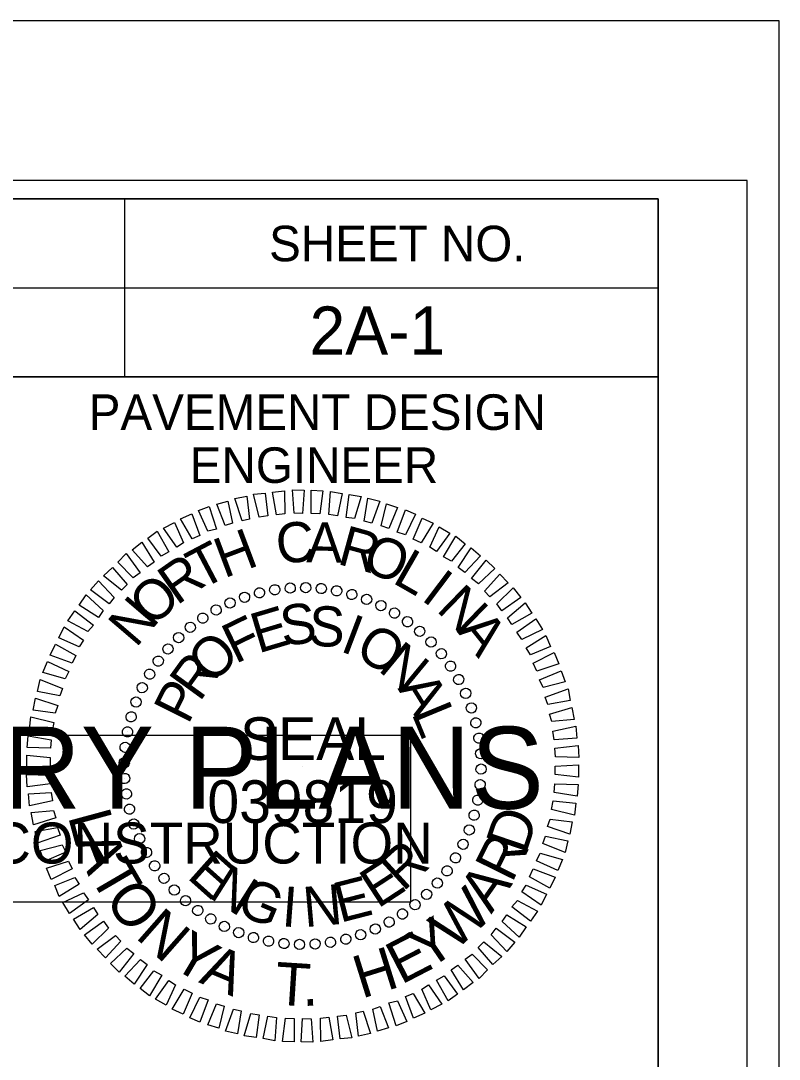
# Model space of a CAD drawing. Extents: x 573786 to 574032, y -53324 to -53148.
# Drawn here: x 574002.74 to 574013.4, y -53229.04 to -53214.45 of the extents above; entities that cross this region are included whole.
import ezdxf

# ---------------------------------------------------------------- set-up
doc = ezdxf.new("R2010")
doc.units = 0
for name, color, linetype in [('Sheet Cutting Line CELL', 7, 'Continuous'), ('Sheet Data Field CELL', 7, 'Continuous'), ('Sheet Plot Border Inside CELL', 7, 'Continuous'), ('Sheet Plot Border Outside CELL', 7, 'Continuous'), ('Sheet Professional Seal CELL', 7, 'Continuous'), ('Sheet Sticker Preliminary CELL', 7, 'Continuous'), ('Sheet Typical CELL', 7, 'Continuous')]:
    doc.layers.add(name, color=color, linetype=linetype)

msp = doc.modelspace()

# ---------------------------------------------------------------- linework, layer by layer
at = {"layer": 'Sheet Cutting Line CELL'}
msp.add_line((574013.401, -53214.447), (573845.001, -53214.447), dxfattribs=at)
at = {"layer": 'Sheet Plot Border Inside CELL'}
msp.add_lwpolyline([(574012.951, -53216.692), (573846.301, -53216.692), (573846.301, -53322.202), (574012.951, -53322.202)], close=True, dxfattribs=at)
at = {"layer": 'Sheet Plot Border Outside CELL'}
msp.add_lwpolyline([(574013.401, -53214.447), (573845.001, -53214.447), (573845.001, -53324.447), (574013.401, -53324.447)], close=True, dxfattribs=at)
at = {"layer": 'Sheet Professional Seal CELL'}
for p, q in [((574005.883, -53222.546), (574005.883, -53222.546)), ((574006.093, -53222.486), (574006.093, -53222.486)), ((574006.313, -53222.446), (574006.313, -53222.446)), ((574006.528, -53222.416), (574006.528, -53222.416)), ((574006.748, -53222.411), (574006.748, -53222.411)), ((574006.968, -53222.426), (574006.968, -53222.426)), ((574007.183, -53222.461), (574007.183, -53222.461)), ((574007.393, -53222.506), (574007.393, -53222.506)), ((574005.683, -53222.626), (574005.683, -53222.626)), ((574007.603, -53222.576), (574007.603, -53222.576)), ((574007.803, -53222.666), (574007.803, -53222.666)), ((574005.298, -53222.841), (574005.298, -53222.841)), ((574005.488, -53222.726), (574005.488, -53222.726)), ((574007.998, -53222.766), (574007.998, -53222.766)), ((574005.123, -53222.966), (574005.123, -53222.966)), ((574008.178, -53222.891), (574008.178, -53222.891)), ((574004.958, -53223.116), (574004.958, -53223.116)), ((574008.353, -53223.026), (574008.353, -53223.026)), ((574004.808, -53223.271), (574004.808, -53223.271)), ((574008.508, -53223.176), (574008.508, -53223.176)), ((574008.658, -53223.341), (574008.658, -53223.341)), ((574004.673, -53223.446), (574004.673, -53223.446)), ((574008.783, -53223.516), (574008.783, -53223.516)), ((574004.548, -53223.626), (574004.548, -53223.626)), ((574008.898, -53223.706), (574008.898, -53223.706)), ((574004.448, -53223.821), (574004.448, -53223.821)), ((574008.998, -53223.901), (574008.998, -53223.901)), ((574004.358, -53224.021), (574004.358, -53224.021)), ((574009.078, -53224.101), (574009.078, -53224.101)), ((574004.288, -53224.231), (574004.288, -53224.231)), ((574004.243, -53224.441), (574004.243, -53224.441)), ((574009.138, -53224.311), (574009.138, -53224.311)), ((574009.178, -53224.531), (574009.178, -53224.531)), ((574004.208, -53224.656), (574004.208, -53224.656)), ((574004.193, -53224.876), (574004.193, -53224.876)), ((574009.208, -53224.746), (574009.208, -53224.746)), ((574006.703, -53224.921), (574006.703, -53224.921)), ((574009.213, -53224.966), (574009.213, -53224.966)), ((574004.198, -53225.096), (574004.198, -53225.096)), ((574004.228, -53225.311), (574004.228, -53225.311)), ((574009.198, -53225.186), (574009.198, -53225.186)), ((574009.163, -53225.401), (574009.163, -53225.401)), ((574004.268, -53225.531), (574004.268, -53225.531)), ((574009.118, -53225.611), (574009.118, -53225.611)), ((574004.328, -53225.741), (574004.328, -53225.741)), ((574009.048, -53225.821), (574009.048, -53225.821)), ((574004.408, -53225.941), (574004.408, -53225.941)), ((574008.958, -53226.021), (574008.958, -53226.021)), ((574004.508, -53226.136), (574004.508, -53226.136)), ((574004.623, -53226.326), (574004.623, -53226.326)), ((574008.858, -53226.216), (574008.858, -53226.216)), ((574008.733, -53226.396), (574008.733, -53226.396)), ((574004.748, -53226.501), (574004.748, -53226.501)), ((574008.598, -53226.571), (574008.598, -53226.571)), ((574004.898, -53226.666), (574004.898, -53226.666)), ((574008.448, -53226.726), (574008.448, -53226.726)), ((574005.053, -53226.816), (574005.053, -53226.816)), ((574008.283, -53226.876), (574008.283, -53226.876)), ((574005.228, -53226.951), (574005.228, -53226.951)), ((574005.408, -53227.076), (574005.408, -53227.076)), ((574008.108, -53227.001), (574008.108, -53227.001)), ((574005.603, -53227.176), (574005.603, -53227.176)), ((574007.723, -53227.216), (574007.723, -53227.216)), ((574007.918, -53227.116), (574007.918, -53227.116)), ((574005.803, -53227.266), (574005.803, -53227.266)), ((574006.013, -53227.336), (574006.013, -53227.336)), ((574007.313, -53227.356), (574007.313, -53227.356)), ((574007.523, -53227.296), (574007.523, -53227.296)), ((574006.223, -53227.381), (574006.223, -53227.381)), ((574006.438, -53227.416), (574006.438, -53227.416)), ((574006.658, -53227.431), (574006.658, -53227.431)), ((574006.878, -53227.426), (574006.878, -53227.426)), ((574007.093, -53227.396), (574007.093, -53227.396))]:
    msp.add_line(p, q, dxfattribs=at)
for points in [[(574006.093, -53221.421), (574006.013, -53221.101), (574006.178, -53221.086), (574006.213, -53221.406)], [(574006.333, -53221.391), (574006.278, -53221.071), (574006.448, -53221.051), (574006.453, -53221.376)], [(574006.583, -53221.366), (574006.558, -53221.041), (574006.723, -53221.046), (574006.703, -53221.371)], [(574006.823, -53221.371), (574006.823, -53221.046), (574006.988, -53221.051), (574006.943, -53221.376)], [(574007.073, -53221.386), (574007.093, -53221.061), (574007.258, -53221.091), (574007.193, -53221.406)], [(574005.613, -53221.541), (574005.498, -53221.241), (574005.653, -53221.196), (574005.718, -53221.506)], [(574005.853, -53221.476), (574005.748, -53221.161), (574005.918, -53221.126), (574005.958, -53221.451)], [(574007.313, -53221.426), (574007.358, -53221.106), (574007.523, -53221.131), (574007.433, -53221.441)], [(574007.568, -53221.481), (574007.618, -53221.156), (574007.788, -53221.196), (574007.673, -53221.506)], [(574007.808, -53221.546), (574007.883, -53221.236), (574008.038, -53221.286), (574007.913, -53221.581)], [(574005.148, -53221.726), (574004.988, -53221.446), (574005.143, -53221.376), (574005.258, -53221.681)], [(574005.368, -53221.621), (574005.238, -53221.331), (574005.388, -53221.271), (574005.493, -53221.591)], [(574008.033, -53221.636), (574008.148, -53221.321), (574008.288, -53221.381), (574008.148, -53221.671)], [(574004.933, -53221.846), (574004.748, -53221.576), (574004.903, -53221.496), (574005.028, -53221.786)], [(574008.258, -53221.731), (574008.383, -53221.436), (574008.538, -53221.506), (574008.368, -53221.786)], [(574004.713, -53221.971), (574004.528, -53221.716), (574004.658, -53221.621), (574004.823, -53221.911)], [(574008.488, -53221.846), (574008.623, -53221.561), (574008.773, -53221.646), (574008.583, -53221.906)], [(574004.523, -53222.121), (574004.308, -53221.881), (574004.443, -53221.776), (574004.618, -53222.056)], [(574008.683, -53221.981), (574008.858, -53221.691), (574008.988, -53221.796), (574008.793, -53222.041)], [(574004.323, -53222.276), (574004.103, -53222.056), (574004.223, -53221.936), (574004.418, -53222.206)], [(574008.888, -53222.131), (574009.073, -53221.856), (574009.203, -53221.966), (574008.983, -53222.201)], [(574009.078, -53222.286), (574009.283, -53222.026), (574009.403, -53222.146), (574009.173, -53222.361)], [(574004.158, -53222.451), (574003.903, -53222.246), (574004.028, -53222.131), (574004.238, -53222.371)], [(574009.258, -53222.461), (574009.473, -53222.226), (574009.593, -53222.346), (574009.333, -53222.541)], [(574003.983, -53222.641), (574003.723, -53222.446), (574003.833, -53222.316), (574004.053, -53222.551)], [(574003.833, -53222.831), (574003.563, -53222.661), (574003.658, -53222.516), (574003.898, -53222.736)], [(574009.433, -53222.641), (574009.663, -53222.416), (574009.768, -53222.551), (574009.503, -53222.741)], [(574009.583, -53222.836), (574009.828, -53222.626), (574009.923, -53222.771), (574009.643, -53222.931)], [(574003.683, -53223.031), (574003.403, -53222.881), (574003.503, -53222.741), (574003.763, -53222.941)], [(574003.563, -53223.246), (574003.278, -53223.121), (574003.353, -53222.966), (574003.623, -53223.151)], [(574009.713, -53223.041), (574009.978, -53222.851), (574010.073, -53223.001), (574009.783, -53223.141)], [(574009.843, -53223.261), (574010.123, -53223.086), (574010.188, -53223.241), (574009.903, -53223.356)], [(574003.463, -53223.476), (574003.153, -53223.361), (574003.228, -53223.206), (574003.513, -53223.366)], [(574009.943, -53223.476), (574010.238, -53223.326), (574010.303, -53223.486), (574009.993, -53223.586)], [(574003.363, -53223.696), (574003.053, -53223.606), (574003.118, -53223.451), (574003.418, -53223.591)], [(574003.288, -53223.936), (574002.978, -53223.871), (574003.013, -53223.706), (574003.328, -53223.831)], [(574010.033, -53223.711), (574010.338, -53223.581), (574010.393, -53223.736), (574010.083, -53223.816)], [(574010.113, -53223.951), (574010.433, -53223.836), (574010.463, -53224.001), (574010.148, -53224.056)], [(574003.223, -53224.176), (574002.913, -53224.136), (574002.948, -53223.966), (574003.263, -53224.071)], [(574010.173, -53224.191), (574010.488, -53224.096), (574010.518, -53224.266), (574010.203, -53224.296)], [(574003.183, -53224.431), (574002.863, -53224.401), (574002.883, -53224.231), (574003.208, -53224.311)], [(574010.218, -53224.431), (574010.543, -53224.361), (574010.558, -53224.531), (574010.238, -53224.551)], [(574003.158, -53224.671), (574002.833, -53224.661), (574002.843, -53224.496), (574003.168, -53224.551)], [(574010.248, -53224.671), (574010.573, -53224.631), (574010.583, -53224.801), (574010.258, -53224.791)], [(574003.153, -53224.921), (574002.828, -53224.936), (574002.828, -53224.766), (574003.153, -53224.801)], [(574010.253, -53224.921), (574010.578, -53224.906), (574010.578, -53225.076), (574010.253, -53225.041)], [(574003.158, -53225.171), (574002.833, -53225.211), (574002.823, -53225.041), (574003.148, -53225.051)], [(574010.248, -53225.171), (574010.573, -53225.181), (574010.563, -53225.346), (574010.238, -53225.291)], [(574003.188, -53225.411), (574002.863, -53225.481), (574002.848, -53225.311), (574003.168, -53225.291)], [(574010.223, -53225.411), (574010.543, -53225.441), (574010.523, -53225.611), (574010.198, -53225.531)], [(574003.233, -53225.651), (574002.918, -53225.746), (574002.888, -53225.576), (574003.203, -53225.546)], [(574010.183, -53225.666), (574010.493, -53225.706), (574010.458, -53225.876), (574010.143, -53225.771)], [(574003.293, -53225.891), (574002.973, -53226.006), (574002.943, -53225.841), (574003.258, -53225.786)], [(574010.118, -53225.906), (574010.428, -53225.971), (574010.393, -53226.136), (574010.078, -53226.011)], [(574003.373, -53226.131), (574003.068, -53226.261), (574003.013, -53226.106), (574003.323, -53226.026)], [(574010.043, -53226.146), (574010.353, -53226.236), (574010.288, -53226.391), (574009.988, -53226.251)], [(574003.463, -53226.366), (574003.168, -53226.516), (574003.103, -53226.356), (574003.413, -53226.256)], [(574003.563, -53226.581), (574003.283, -53226.756), (574003.218, -53226.601), (574003.503, -53226.486)], [(574009.943, -53226.366), (574010.253, -53226.481), (574010.178, -53226.636), (574009.893, -53226.476)], [(574009.843, -53226.596), (574010.128, -53226.721), (574010.053, -53226.876), (574009.783, -53226.691)], [(574003.693, -53226.801), (574003.428, -53226.991), (574003.333, -53226.841), (574003.623, -53226.701)], [(574003.823, -53227.006), (574003.578, -53227.216), (574003.483, -53227.071), (574003.763, -53226.911)], [(574009.723, -53226.811), (574010.003, -53226.961), (574009.903, -53227.101), (574009.643, -53226.901)], [(574009.573, -53227.011), (574009.843, -53227.181), (574009.748, -53227.326), (574009.508, -53227.106)], [(574003.973, -53227.201), (574003.743, -53227.426), (574003.638, -53227.291), (574003.903, -53227.101)], [(574009.423, -53227.201), (574009.683, -53227.396), (574009.573, -53227.526), (574009.353, -53227.291)], [(574004.148, -53227.381), (574003.933, -53227.616), (574003.813, -53227.496), (574004.073, -53227.301)], [(574004.328, -53227.556), (574004.123, -53227.816), (574004.003, -53227.696), (574004.233, -53227.481)], [(574009.248, -53227.391), (574009.503, -53227.596), (574009.378, -53227.711), (574009.168, -53227.471)], [(574004.518, -53227.711), (574004.333, -53227.986), (574004.203, -53227.876), (574004.423, -53227.641)], [(574009.083, -53227.566), (574009.303, -53227.786), (574009.183, -53227.906), (574008.988, -53227.636)], [(574004.723, -53227.861), (574004.548, -53228.151), (574004.418, -53228.046), (574004.613, -53227.801)], [(574008.883, -53227.721), (574009.098, -53227.961), (574008.963, -53228.066), (574008.788, -53227.786)], [(574004.918, -53227.996), (574004.783, -53228.281), (574004.633, -53228.196), (574004.823, -53227.936)], [(574008.693, -53227.871), (574008.878, -53228.126), (574008.748, -53228.221), (574008.583, -53227.931)], [(574005.148, -53228.111), (574005.023, -53228.406), (574004.868, -53228.336), (574005.038, -53228.056)], [(574008.473, -53227.996), (574008.658, -53228.266), (574008.503, -53228.346), (574008.378, -53228.056)], [(574005.373, -53228.206), (574005.258, -53228.521), (574005.118, -53228.461), (574005.258, -53228.171)], [(574008.038, -53228.221), (574008.168, -53228.511), (574008.018, -53228.571), (574007.913, -53228.251)], [(574008.258, -53228.116), (574008.418, -53228.396), (574008.263, -53228.466), (574008.148, -53228.161)], [(574005.598, -53228.296), (574005.523, -53228.606), (574005.368, -53228.556), (574005.493, -53228.261)], [(574005.838, -53228.361), (574005.788, -53228.686), (574005.618, -53228.646), (574005.733, -53228.336)], [(574007.553, -53228.366), (574007.658, -53228.681), (574007.488, -53228.716), (574007.448, -53228.391)], [(574007.793, -53228.301), (574007.908, -53228.601), (574007.753, -53228.646), (574007.688, -53228.336)], [(574006.093, -53228.416), (574006.048, -53228.736), (574005.883, -53228.711), (574005.973, -53228.401)], [(574006.333, -53228.456), (574006.313, -53228.781), (574006.148, -53228.751), (574006.213, -53228.436)], [(574006.583, -53228.471), (574006.583, -53228.796), (574006.418, -53228.791), (574006.463, -53228.466)], [(574006.823, -53228.476), (574006.848, -53228.801), (574006.683, -53228.796), (574006.703, -53228.471)], [(574007.073, -53228.451), (574007.128, -53228.771), (574006.958, -53228.791), (574006.953, -53228.466)], [(574007.313, -53228.421), (574007.393, -53228.741), (574007.228, -53228.756), (574007.193, -53228.436)]]:
    msp.add_lwpolyline(points, close=True, dxfattribs=at)
for centre, major_axis in [((574006.31, -53222.443), (-0.0113, 0.0711)), ((574006.528, -53222.419), (-0.005, 0.0718)), ((574006.746, -53222.413), (0.0013, 0.072)), ((574006.965, -53222.426), (0.0075, 0.0716)), ((574007.181, -53222.459), (0.0137, 0.0707)), ((574005.683, -53222.629), (-0.0293, 0.0658)), ((574005.886, -53222.549), (-0.0234, 0.0681)), ((574006.096, -53222.487), (-0.0174, 0.0699)), ((574007.394, -53222.51), (0.0198, 0.0692)), ((574007.601, -53222.579), (0.0258, 0.0672)), ((574005.487, -53222.727), (-0.0349, 0.063)), ((574007.802, -53222.666), (0.0316, 0.0647)), ((574007.994, -53222.771), (0.0371, 0.0617)), ((574005.3, -53222.841), (-0.0403, 0.0597)), ((574008.177, -53222.892), (0.0423, 0.0582)), ((574005.124, -53222.971), (-0.0453, 0.056)), ((574008.348, -53223.028), (0.0472, 0.0543)), ((574004.96, -53223.116), (-0.05, 0.0518)), ((574008.507, -53223.178), (0.0518, 0.05)), ((574004.81, -53223.275), (-0.0543, 0.0472)), ((574008.652, -53223.342), (0.056, 0.0453)), ((574004.674, -53223.446), (-0.0582, 0.0423)), ((574004.553, -53223.629), (-0.0617, 0.0371)), ((574008.782, -53223.518), (0.0597, 0.0403)), ((574008.896, -53223.705), (0.063, 0.0349)), ((574004.448, -53223.821), (-0.0647, 0.0316)), ((574008.994, -53223.9), (0.0658, 0.0293)), ((574004.361, -53224.022), (-0.0672, 0.0258)), ((574004.292, -53224.229), (-0.0692, 0.0198)), ((574009.074, -53224.104), (0.0681, 0.0234)), ((574009.136, -53224.314), (0.0699, 0.0174)), ((574004.241, -53224.442), (-0.0707, 0.0137)), ((574004.208, -53224.658), (-0.0716, 0.0075)), ((574009.18, -53224.528), (0.0711, 0.0113)), ((574009.205, -53224.746), (0.0718, 0.005)), ((574004.195, -53224.877), (-0.072, 0.0013)), ((574004.201, -53225.096), (-0.0718, -0.005)), ((574009.21, -53224.964), (0.072, -0.0013)), ((574009.197, -53225.183), (0.0716, -0.0075)), ((574004.226, -53225.313), (-0.0711, -0.0113)), ((574009.165, -53225.399), (0.0707, -0.0137)), ((574004.269, -53225.527), (-0.0699, -0.0174)), ((574009.113, -53225.612), (0.0692, -0.0198)), ((574004.331, -53225.737), (-0.0681, -0.0234)), ((574009.044, -53225.819), (0.0672, -0.0258)), ((574004.411, -53225.941), (-0.0658, -0.0293)), ((574004.509, -53226.136), (-0.063, -0.0349)), ((574008.957, -53226.02), (0.0647, -0.0316)), ((574008.852, -53226.212), (0.0617, -0.0371)), ((574004.623, -53226.323), (-0.0597, -0.0403)), ((574008.732, -53226.395), (0.0582, -0.0423)), ((574004.754, -53226.499), (-0.056, -0.0453)), ((574008.595, -53226.566), (0.0543, -0.0472)), ((574004.899, -53226.663), (-0.0518, -0.05)), ((574005.057, -53226.813), (-0.0472, -0.0543)), ((574008.445, -53226.725), (0.05, -0.0518)), ((574005.228, -53226.95), (-0.0423, -0.0582)), ((574008.105, -53227), (0.0403, -0.0597)), ((574008.281, -53226.87), (0.0453, -0.056)), ((574005.411, -53227.07), (-0.0371, -0.0617)), ((574007.919, -53227.114), (0.0349, -0.063)), ((574005.603, -53227.175), (-0.0316, -0.0647)), ((574005.804, -53227.262), (-0.0258, -0.0672)), ((574007.519, -53227.292), (0.0234, -0.0681)), ((574007.723, -53227.212), (0.0293, -0.0658)), ((574006.011, -53227.331), (-0.0198, -0.0692)), ((574006.224, -53227.382), (-0.0137, -0.0707)), ((574006.44, -53227.415), (-0.0075, -0.0716)), ((574006.659, -53227.428), (-0.0013, -0.072)), ((574006.878, -53227.422), (0.005, -0.0718)), ((574007.095, -53227.398), (0.0113, -0.0711)), ((574007.309, -53227.354), (0.0174, -0.0699))]:
    msp.add_ellipse(centre, major_axis=major_axis, ratio=0.999708, dxfattribs=at)
at = {"layer": 'Sheet Sticker Preliminary CELL'}
msp.add_lwpolyline([(573993.52, -53226.836), (573993.52, -53224.486), (574008.22, -53224.486), (574008.22, -53226.836)], close=True, dxfattribs=at)
at = {"layer": 'Sheet Typical CELL'}
for p, q in [((574004.201, -53216.952), (574004.201, -53219.452)), ((573991.696, -53218.202), (574011.701, -53218.202))]:
    msp.add_line(p, q, dxfattribs=at)
for points in [[(574011.701, -53216.947), (573861.701, -53216.947), (573861.701, -53321.947), (574011.701, -53321.947)], [(573991.696, -53216.947), (574011.701, -53216.947), (574011.701, -53219.452), (573991.696, -53219.452)], [(574001.701, -53219.452), (574011.701, -53219.452), (574011.701, -53230.702), (574001.701, -53230.702)]]:
    msp.add_lwpolyline(points, close=True, dxfattribs=at)

# ---------------------------------------------------------------- texts
at = {"layer": 'Sheet Data Field CELL'}
msp.add_text('2A-1', height=0.675, dxfattribs=at).set_placement((574006.8, -53219.137))
at = {"layer": 'Sheet Professional Seal CELL'}
for s, height, rotation, p in [('C', 0.564, 6.2199, (574006.358, -53222.086)), ('A', 0.564, 359.0203, (574006.753, -53222.056)), ('H', 0.564, 20.6195, (574005.598, -53222.286)), ('R', 0.564, 344.6211, (574007.173, -53222.076)), ('T', 0.564, 27.8198, (574005.273, -53222.451)), ('O', 0.564, 337.4212, (574007.508, -53222.151)), ('L', 0.564, 330.2209, (574007.948, -53222.336)), ('R', 0.564, 35.0205, (574004.933, -53222.671)), ('I', 0.564, 323.0201, (574008.353, -53222.576)), ('O', 0.564, 42.2217, (574004.588, -53222.981)), ('N', 0.564, 315.8189, (574008.568, -53222.731)), ('N', 0.564, 49.4235, (574004.358, -53223.271)), ('E', 0.564, 16.6111, (574006.078, -53223.341)), ('S', 0.564, 7.2556, (574006.423, -53223.236)), ('S', 0.564, 357.9004, (574006.783, -53223.231)), ('F', 0.564, 25.967, (574005.758, -53223.491)), ('I', 0.564, 339.1896, (574007.213, -53223.301)), ('A', 0.564, 308.6172, (574008.863, -53223.026)), ('O', 0.564, 329.8335, (574007.413, -53223.371)), ('O', 0.564, 44.6812, (574005.428, -53223.786)), ('N', 0.564, 320.4766, (574007.748, -53223.571)), ('R', 0.564, 54.0397, (574005.253, -53224.031)), ('A', 0.564, 301.7603, (574008.033, -53223.831)), ('P', 0.564, 63.3989, (574005.093, -53224.351)), ('L', 0.564, 292.4008, (574008.228, -53224.176)), ('SEAL', 0.5998, 360, (574005.823, -53224.836)), ('L', 0.6, 285.1742, (574003.402, -53225.625)), ('D', 0.6, 71.2248, (574009.834, -53226.18)), ('R', 0.6, 63.7445, (574009.643, -53226.577)), ('A', 0.6, 291.449, (574003.499, -53225.981)), ('R', 0.564, 42.4814, (574008.113, -53226.696)), ('T', 0.6, 300.2893, (574003.7, -53226.461)), ('E', 0.564, 318.2769, (574005.063, -53226.486)), ('N', 0.564, 327.634, (574005.363, -53226.756)), ('E', 0.564, 33.1241, (574007.758, -53226.931)), ('E', 0.564, 14.4118, (574007.228, -53227.126)), ('A', 0.6, 54.9042, (574009.354, -53227.009)), ('O', 0.6, 307.0895, (574003.903, -53226.806)), ('G', 0.564, 336.9902, (574005.743, -53226.981)), ('I', 0.564, 355.7012, (574006.398, -53227.171)), ('N', 0.564, 5.0564, (574006.733, -53227.186)), ('W', 0.6, 42.3701, (574008.837, -53227.535)), ('N', 0.6, 318.6499, (574004.338, -53227.328)), ('Y', 0.6, 34.4571, (574008.457, -53227.804)), ('Y', 0.6, 329.3758, (574004.827, -53227.727)), ('E', 0.6, 27.3478, (574008.087, -53227.999)), ('A', 0.6, 337.2888, (574005.231, -53227.958)), ('H', 0.6, 17.3638, (574007.532, -53228.192)), ('T', 0.6, 356.3294, (574006.303, -53228.272)), ('.', 0.6, 3.1297, (574006.702, -53228.296))]:
    msp.add_text(s, height=height, rotation=rotation, dxfattribs=at).set_placement(p)
msp.add_text('039819', height=0.5998, dxfattribs=at).set_placement((574005.364, -53225.721))
at = {"layer": 'Sheet Sticker Preliminary CELL'}
for s, height, p in [('PRELIMINARY PLANS', 1.152, (573994.17, -53225.521)), ('DO NOT USE FOR CONSTRUCTION', 0.576, (573995.48, -53226.291))]:
    msp.add_text(s, height=height, dxfattribs=at).set_placement(p)
at = {"layer": 'Sheet Typical CELL'}
for s, height, p in [('SHEET NO.', 0.5, (574006.231, -53217.827)), ('PAVEMENT DESIGN', 0.50001, (574003.696, -53220.197)), ('ENGINEER', 0.5, (574005.116, -53220.942))]:
    msp.add_text(s, height=height, dxfattribs=at).set_placement(p)

doc.saveas('drawing.dxf')
